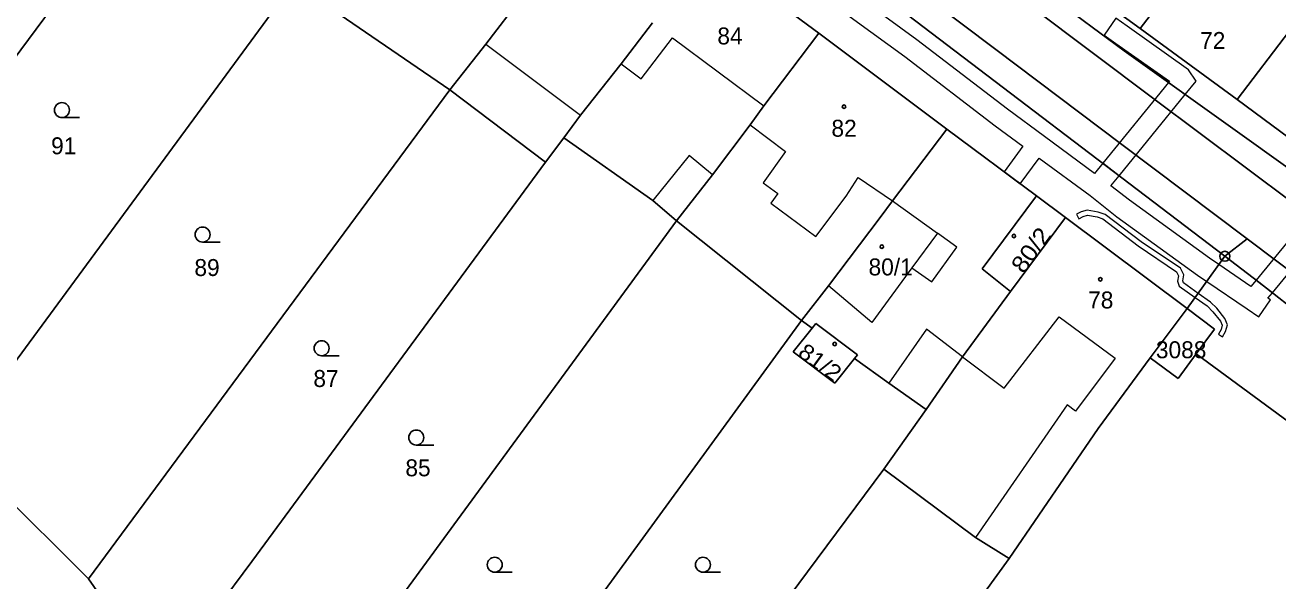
# Model space of a CAD drawing. Extents: x -606517 to -602431, y -1183120 to -1179397.
# Drawn here: x -605244.5 to -605119, y -1181147.4 to -1181091.7 of the extents above; entities that cross this region are included whole.
import ezdxf
from ezdxf.enums import TextEntityAlignment as Align

# ---------------------------------------------------------------- set-up
doc = ezdxf.new("R2010")
doc.units = 0
doc.header["$LTSCALE"] = 0.68
for name, color, linetype, lineweight in [('1', 7, 'Continuous', 25), ('13', 7, 'Continuous', 13), ('3', 7, 'Continuous', 25), ('4', 7, 'Continuous', 13), ('5', 7, 'Continuous', 25), ('8', 7, 'Continuous', 25)]:
    doc.layers.add(name, color=color, linetype=linetype, lineweight=lineweight)
doc.layers.add('2', color=7, linetype='Continuous')

msp = doc.modelspace()

# ---------------------------------------------------------------- linework, layer by layer
at = {"layer": '1'}
for p, q in [((-605169.93, -1181067.9), (-605134.38, -1181094.27)), ((-605147.22, -1181094.13), (-605170.96, -1181076.23)), ((-605231.85, -1181076.56), (-605265.64, -1181122.03)), ((-605164.97, -1181092.49), (-605176.13, -1181084.23)), ((-605124.28, -1181114.86), (-605163.73, -1181084.82)), ((-605142.5, -1181084.97), (-605132.75, -1181092.02)), ((-605132.75, -1181092.02), (-605127.48, -1181085.14)), ((-605251.63, -1181133.76), (-605217.59, -1181087.45)), ((-605201.94, -1181098.18), (-605217.59, -1181087.45)), ((-605193.22, -1181086.91), (-605198.33, -1181093.61)), ((-605143.76, -1181089.79), (-605131.39, -1181099.08)), ((-605184.76, -1181095.58), (-605181.62, -1181091.47)), ((-605164.97, -1181092.49), (-605170.46, -1181099.77)), ((-605152.14, -1181102.11), (-605164.97, -1181092.49)), ((-605132.75, -1181092.02), (-605123.05, -1181099.14)), ((-605117.81, -1181092.28), (-605123.05, -1181099.14)), ((-605198.33, -1181093.61), (-605201.94, -1181098.18)), ((-605134.61, -1181103.64), (-605147.22, -1181094.13)), ((-605134.38, -1181094.27), (-605115.39, -1181107.85)), ((-605188.83, -1181100.73), (-605184.76, -1181095.58)), ((-605201.94, -1181098.18), (-605238.13, -1181147.19)), ((-605192.36, -1181105.44), (-605201.94, -1181098.18)), ((-605131.39, -1181099.08), (-605117.47, -1181109.49)), ((-605170.46, -1181099.77), (-605171.83, -1181101.67)), ((-605123.05, -1181099.14), (-605113.42, -1181106.3)), ((-605190.53, -1181103), (-605188.83, -1181100.73)), ((-605171.83, -1181101.67), (-605175.62, -1181106.71)), ((-605143.17, -1181108.8), (-605152.14, -1181102.11)), ((-605192.36, -1181105.44), (-605190.53, -1181103)), ((-605181.59, -1181109.28), (-605190.53, -1181103)), ((-605134.61, -1181103.64), (-605122.06, -1181113.11)), ((-605221.78, -1181145.44), (-605192.36, -1181105.44)), ((-605175.62, -1181106.71), (-605179.23, -1181111.29)), ((-605143.17, -1181108.8), (-605148.6, -1181116.13)), ((-605140.26, -1181110.97), (-605143.17, -1181108.8)), ((-605179.23, -1181111.29), (-605181.59, -1181109.28)), ((-605179.23, -1181111.29), (-605222.31, -1181170.1)), ((-605166.69, -1181121.29), (-605179.23, -1181111.29)), ((-605163.99, -1181117.82), (-605158.82, -1181110.96)), ((-605140.26, -1181110.97), (-605145.75, -1181118.4)), ((-605128.05, -1181120.1), (-605140.26, -1181110.97)), ((-605122.06, -1181113.11), (-605124.28, -1181114.86)), ((-605122.06, -1181113.11), (-605104.5, -1181126.35)), ((-605124.28, -1181114.86), (-605125.81, -1181116.98)), ((-605120.87, -1181117.45), (-605124.28, -1181114.86)), ((-605148.6, -1181116.13), (-605145.75, -1181118.4)), ((-605166.69, -1181121.29), (-605163.99, -1181117.82)), ((-605125.81, -1181116.98), (-605128.05, -1181120.1)), ((-605112.86, -1181123.73), (-605120.87, -1181117.45)), ((-605145.75, -1181118.4), (-605150.56, -1181124.92)), ((-605128.05, -1181120.1), (-605131.75, -1181125.03)), ((-605125.33, -1181122.17), (-605128.05, -1181120.1)), ((-605212.18, -1181183.65), (-605166.69, -1181121.29)), ((-605165.63, -1181122.05), (-605166.69, -1181121.29)), ((-605165.63, -1181122.05), (-605165.26, -1181121.59)), ((-605165.26, -1181121.59), (-605161.1, -1181124.73)), ((-605167.52, -1181124.44), (-605165.63, -1181122.05)), ((-605127.15, -1181124.63), (-605125.33, -1181122.17)), ((-605163.35, -1181127.58), (-605167.52, -1181124.44)), ((-605161.39, -1181125.1), (-605163.35, -1181127.58)), ((-605161.1, -1181124.73), (-605161.39, -1181125.1)), ((-605157.96, -1181127.56), (-605161.39, -1181125.1)), ((-605150.56, -1181124.92), (-605154.2, -1181130.21)), ((-605131.75, -1181125.03), (-605136.98, -1181132.12)), ((-605128.97, -1181127.09), (-605131.75, -1181125.03)), ((-605127.15, -1181124.63), (-605128.97, -1181127.09)), ((-605116.67, -1181132.36), (-605127.15, -1181124.63)), ((-605154.2, -1181130.21), (-605157.96, -1181127.56)), ((-605154.2, -1181130.21), (-605158.46, -1181136.18)), ((-605136.98, -1181132.12), (-605145.9, -1181145.15)), ((-605238.13, -1181147.19), (-605251.63, -1181133.76)), ((-605158.46, -1181136.18), (-605203.38, -1181196.61)), ((-605149.25, -1181143.04), (-605158.46, -1181136.18)), ((-605145.9, -1181145.15), (-605149.25, -1181143.04)), ((-605230.84, -1181157.66), (-605221.78, -1181145.44)), ((-605145.9, -1181145.15), (-605153.62, -1181155.73)), ((-605230.84, -1181157.66), (-605238.13, -1181147.19))]:
    msp.add_line(p, q, dxfattribs=at)
msp.add_lwpolyline([(-605158.82, -1181110.96), (-605157.59, -1181109.29), (-605152.14, -1181102.11)], dxfattribs=at)
at = {"layer": '13'}
for points in [[(-605119.51, -1181118.51), (-605121.14, -1181117.24), (-605121.67, -1181117.89), (-605124.88, -1181115.69), (-605125.81, -1181115.06), (-605133.83, -1181109.25), (-605135.7, -1181107.8), (-605134.88, -1181106.79), (-605136.52, -1181105.54), (-605137.34, -1181106.55), (-605142.35, -1181102.86), (-605146.06, -1181100.11), (-605155.13, -1181093.16), (-605164.77, -1181086.12)], [(-605165.22, -1181088.34), (-605156.33, -1181094.84), (-605147.28, -1181101.77), (-605144.52, -1181103.82), (-605146.41, -1181106.38), (-605144.78, -1181107.6), (-605142.88, -1181105.02), (-605137.79, -1181108.77), (-605135.09, -1181110.89), (-605127.01, -1181116.74), (-605126.09, -1181117.37), (-605122.06, -1181120.12), (-605120.87, -1181120.93), (-605119.71, -1181119.23), (-605119.96, -1181119.06), (-605119.51, -1181118.51)]]:
    msp.add_lwpolyline(points, dxfattribs=at)
for points in [[(-605135.22, -1181091.01), (-605136.38, -1181092.71), (-605135.2, -1181093.52), (-605129.83, -1181097.32), (-605129.93, -1181097.45), (-605128.26, -1181098.65), (-605127.17, -1181097.31), (-605127.91, -1181096.16), (-605134.06, -1181091.8)], [(-605134.88, -1181106.79), (-605128.26, -1181098.65), (-605129.93, -1181097.45), (-605136.52, -1181105.54)], [(-605119.51, -1181118.51), (-605112.47, -1181109.94), (-605111.68, -1181108.98), (-605111.12, -1181107.96), (-605112.8, -1181106.75), (-605113.37, -1181107.78), (-605114.15, -1181108.73), (-605121.14, -1181117.24)], [(-605138.91, -1181111.09), (-605138.49, -1181110.86), (-605138.05, -1181110.74), (-605137.08, -1181110.92), (-605136.52, -1181111.1), (-605132.98, -1181113.8), (-605129.12, -1181116.4), (-605128.92, -1181116.8), (-605129.02, -1181117.36), (-605128.86, -1181117.85), (-605127.25, -1181118.98), (-605126.05, -1181119.82), (-605125.48, -1181120.41), (-605124.71, -1181121.36), (-605124.55, -1181121.76), (-605124.66, -1181122.2), (-605124.93, -1181122.65), (-605124.52, -1181122.92), (-605124.2, -1181122.38), (-605124.03, -1181121.72), (-605124.27, -1181121.1), (-605125.1, -1181120.07), (-605125.73, -1181119.44), (-605126.96, -1181118.58), (-605128.44, -1181117.53), (-605128.5, -1181117.32), (-605128.4, -1181116.72), (-605128.72, -1181116.06), (-605132.68, -1181113.4), (-605136.28, -1181110.66), (-605136.96, -1181110.44), (-605138.07, -1181110.22), (-605138.69, -1181110.4), (-605139.15, -1181110.65)]]:
    msp.add_lwpolyline(points, close=True, dxfattribs=at)
at = {"layer": '3'}
for p, q in [((-605240.803, -1181100.96), (-605239.053, -1181100.96)), ((-605226.713, -1181113.43), (-605224.963, -1181113.43)), ((-605214.783, -1181124.82), (-605213.033, -1181124.82)), ((-605205.303, -1181133.77), (-605203.553, -1181133.77)), ((-605197.443, -1181146.52), (-605195.693, -1181146.52)), ((-605176.573, -1181146.52), (-605174.823, -1181146.52))]:
    msp.add_line(p, q, dxfattribs=at)
for centre in [(-605240.8029, -1181100.2098), (-605226.7129, -1181112.6798), (-605214.7829, -1181124.0698), (-605205.3029, -1181133.0198), (-605197.4429, -1181145.7698), (-605176.5729, -1181145.7698)]:
    msp.add_circle(centre, 0.75, dxfattribs=at)
at = {"layer": '4'}
for p, q in [((-605198.33, -1181093.61), (-605188.83, -1181100.73)), ((-605182.78, -1181097.09), (-605179.62, -1181092.95)), ((-605179.62, -1181092.95), (-605170.46, -1181099.77)), ((-605184.76, -1181095.58), (-605182.78, -1181097.09)), ((-605171.83, -1181101.67), (-605168.29, -1181104.37)), ((-605177.95, -1181104.76), (-605181.59, -1181109.28)), ((-605175.62, -1181106.71), (-605177.95, -1181104.76)), ((-605168.29, -1181104.37), (-605170.55, -1181107.5)), ((-605170.55, -1181107.5), (-605169.07, -1181108.55)), ((-605162.24, -1181108.82), (-605161.02, -1181106.96)), ((-605161.02, -1181106.96), (-605157.59, -1181109.29)), ((-605169.07, -1181108.55), (-605169.79, -1181109.54)), ((-605165.28, -1181112.86), (-605162.24, -1181108.82)), ((-605169.79, -1181109.54), (-605165.28, -1181112.86)), ((-605157.59, -1181109.29), (-605153.07, -1181112.54)), ((-605153.07, -1181112.54), (-605155.63, -1181116.01)), ((-605151.13, -1181113.93), (-605153.07, -1181112.54)), ((-605153.65, -1181117.43), (-605151.13, -1181113.93)), ((-605155.63, -1181116.01), (-605159.66, -1181121.48)), ((-605155.63, -1181116.01), (-605153.65, -1181117.43)), ((-605159.66, -1181121.48), (-605163.99, -1181117.82)), ((-605146.4, -1181128.06), (-605140.89, -1181120.94)), ((-605140.89, -1181120.94), (-605135.28, -1181125.08)), ((-605154.17, -1181122.16), (-605157.96, -1181127.56)), ((-605150.56, -1181124.92), (-605154.17, -1181122.16)), ((-605150.56, -1181124.92), (-605146.4, -1181128.06)), ((-605135.28, -1181125.08), (-605139.23, -1181130.37)), ((-605140.08, -1181129.74), (-605149.25, -1181143.04)), ((-605139.23, -1181130.37), (-605140.08, -1181129.74))]:
    msp.add_line(p, q, dxfattribs=at)
at = {"layer": '5'}
for centre in [(-605162.4368, -1181099.8692), (-605145.4168, -1181112.8292), (-605158.6468, -1181113.8992), (-605136.7568, -1181117.1592), (-605163.3768, -1181123.6492)]:
    msp.add_circle(centre, 0.175, dxfattribs=at)
at = {"layer": '8'}
for radius in [0.5, 0.0303]:
    msp.add_circle((-605124.28, -1181114.8599), radius, dxfattribs=at)

# ---------------------------------------------------------------- texts
at = {"layer": '2'}
for s, p in [('84', (-605175.13, -1181093.625)), ('72', (-605126.76, -1181094.085)), ('82', (-605163.7, -1181102.875)), ('91', (-605241.89, -1181104.635)), ('89', (-605227.53, -1181116.835)), ('80/1', (-605159.98, -1181116.775)), ('78', (-605137.98, -1181120.085)), ('87', (-605215.61, -1181127.955)), ('85', (-605206.39, -1181136.905))]:
    msp.add_text(s, height=1.7, dxfattribs=at).set_placement(p)
at = {"layer": '2', "width": 1.1}
for s, height, rotation, p in [('80/2', 1.7, 54, (-605144.446, -1181116.699)), ('81/2', 1.61, 324, (-605167.176, -1181124.765))]:
    msp.add_text(s, height=height, rotation=rotation, dxfattribs=at).set_placement(p)
at = {"layer": '2'}
msp.add_text('3088', height=1.7, dxfattribs=at).set_placement((-605128.66, -1181125.075), align=Align.CENTER)

doc.saveas('drawing.dxf')
